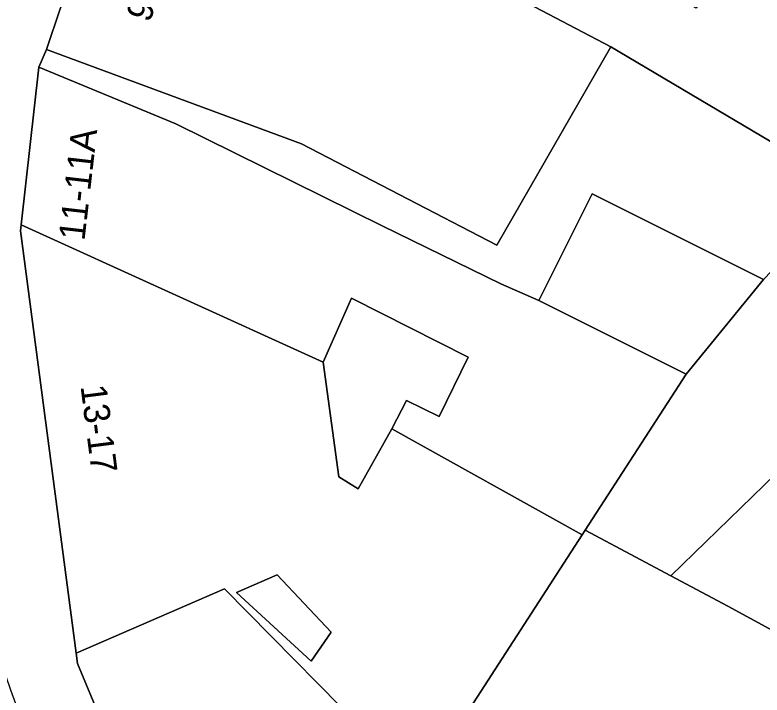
# Model space of a CAD drawing. Extents: x 160663 to 161506, y 382245 to 383291.
# Drawn here: x 161129.57 to 161158.3, y 383159.05 to 383185.21 of the extents above; entities that cross this region are included whole.
import ezdxf

# ---------------------------------------------------------------- set-up
doc = ezdxf.new("R2010")
doc.units = 0
for name, color, linetype in [('IMGEO_Erf', 7, 'Continuous'), ('IMGEO_Groenvoorziening', 7, 'Continuous'), ('IMGEO_Pand', 7, 'Continuous'), ('IMGEO_Pand_nummerreeks', 7, 'Continuous'), ('IMGEO_Parkeervlak_open', 7, 'Continuous'), ('IMGEO_Rijbaan_lokaal_open', 7, 'Continuous'), ('IMGEO_Woonerf_open', 7, 'Continuous')]:
    doc.layers.add(name, color=color, linetype=linetype)

msp = doc.modelspace()

# ---------------------------------------------------------------- linework, layer by layer
at = {"layer": 'IMGEO_Erf'}
for points in [[(161152.489, 383183.975), (161148.098, 383176.349), (161140.589, 383180.249), (161130.789, 383183.88), (161130.489, 383183.198), (161135.759, 383181.024), (161143.687, 383177.09), (161148.256, 383174.862), (161149.712, 383174.226), (161151.763, 383178.33), (161158.353, 383175.037), (161161.697, 383178.516)], [(161146.994, 383172.049), (161142.518, 383174.315), (161141.423, 383171.856), (161142.026, 383167.449), (161142.775, 383166.983), (161144.065, 383169.294), (161144.626, 383170.374), (161145.885, 383169.763)], [(161141.729, 383161.474), (161139.651, 383163.673), (161138.095, 383162.998), (161140.959, 383160.361)]]:
    msp.add_lwpolyline(points, close=True, dxfattribs=at)
at = {"layer": 'IMGEO_Groenvoorziening'}
msp.add_lwpolyline([(161159.601, 383161.046), (161156.987, 383162.473), (161154.786, 383163.643), (161151.498, 383165.39), (161151.378, 383165.212), (161146.783, 383158.104), (161149.389, 383151.959), (161150.771, 383148.7), (161150.848, 383148.779), (161151.214, 383148.74), (161151.442, 383143.355), (161142.883, 383135.27), (161146.227, 383132.301), (161147.528, 383133.493), (161149.889, 383137.24), (161153.216, 383142.573), (161155.564, 383146.324), (161155.876, 383146.12), (161165.215, 383155.885)], dxfattribs=at)
at = {"layer": 'IMGEO_Pand'}
for points in [[(161172.367, 383200.749), (161171.844, 383201.255), (161159.377, 383211.995), (161158.058, 383210.285), (161155.834, 383211.816), (161154.669, 383210.217), (161147.146, 383215.757), (161145.479, 383213.282), (161139.653, 383204.63), (161139.801, 383204.468), (161148.222, 383200.282), (161153.886, 383196.391), (161151.659, 383193.084), (161157.001, 383189.472), (161157.811, 383188.924), (161155.764, 383185.471), (161150.54, 383188.404), (161149.011, 383185.817), (161152.489, 383183.975), (161161.697, 383178.516), (161162.427, 383178.083), (161166.075, 383183.277), (161162.938, 383185.44), (161160.536, 383187.097)], [(161134.132, 383192.246), (161131.314, 383185.435), (161130.789, 383183.88), (161140.589, 383180.249), (161148.098, 383176.349), (161152.489, 383183.975), (161149.011, 383185.817), (161143.541, 383188.713)], [(161143.687, 383177.09), (161135.759, 383181.024), (161130.489, 383183.198), (161129.809, 383177.129), (161141.423, 383171.856), (161142.518, 383174.315), (161146.994, 383172.049), (161145.885, 383169.763), (161144.626, 383170.374), (161144.065, 383169.294), (161151.378, 383165.212), (161151.498, 383165.39), (161155.385, 383171.391), (161149.712, 383174.226), (161148.256, 383174.862)], [(161155.385, 383171.391), (161158.353, 383175.037), (161151.763, 383178.33), (161149.712, 383174.226)], [(161141.423, 383171.856), (161129.809, 383177.129), (161129.783, 383176.901), (161131.927, 383160.664), (161137.626, 383163.141), (161143.896, 383156.786), (161145.179, 383155.593), (161145.348, 383155.898), (161146.783, 383158.104), (161151.378, 383165.212), (161144.065, 383169.294), (161142.775, 383166.983), (161142.026, 383167.449)], [(161139.651, 383163.673), (161141.729, 383161.474), (161140.959, 383160.361), (161138.095, 383162.998)], [(161131.927, 383160.664), (161131.982, 383160.267), (161134.843, 383153.401), (161143.896, 383156.786), (161137.626, 383163.141)]]:
    msp.add_lwpolyline(points, close=True, dxfattribs=at)
at = {"layer": 'IMGEO_Parkeervlak_open'}
msp.add_lwpolyline([(161179.091, 383187.153), (161175.47, 383190.87), (161165.765, 383181.237), (161162.427, 383178.083), (161161.697, 383178.516), (161158.353, 383175.037), (161155.385, 383171.391), (161151.498, 383165.39), (161154.786, 383163.643), (161163.312, 383171.916), (161171.06, 383179.398)], close=True, dxfattribs=at)
at = {"layer": 'IMGEO_Rijbaan_lokaal_open'}
msp.add_lwpolyline([(161206.066, 383159.432), (161201.563, 383163.94), (161200.163, 383165.469), (161189.424, 383176.545), (161179.091, 383187.153), (161171.06, 383179.398), (161163.312, 383171.916), (161154.786, 383163.643), (161156.987, 383162.473), (161159.601, 383161.046)], dxfattribs=at)
at = {"layer": 'IMGEO_Woonerf_open'}
msp.add_lwpolyline([(161137.518, 383146.979), (161134.843, 383153.401), (161131.982, 383160.267), (161131.927, 383160.664), (161129.783, 383176.901), (161129.809, 383177.129), (161130.489, 383183.198), (161130.789, 383183.88), (161131.314, 383185.435), (161134.132, 383192.246), (161135.412, 383195.339), (161136.378, 383197.673), (161136.869, 383198.648), (161139.406, 383203.684), (161139.801, 383204.468), (161139.653, 383204.63), (161138.74, 383205.154), (161143.158, 383214.429), (161142.031, 383214.987), (161141.728, 383215.125), (161141.644, 383214.953), (161140.933, 383213.502), (161130.888, 383192.701)], dxfattribs=at)
for centre, radius, start, end in [((161170.895, 383174.782), 43.837, 155.8726, 168.4568), ((161170.895, 383174.782), 43.837, 155.8726, 168.4568), ((161171.449, 383174.177), 44.609, 179.4958, 202.4128), ((161171.449, 383174.177), 44.609, 179.4958, 202.4128)]:
    msp.add_arc(centre, radius, start, end, dxfattribs=at)

# ---------------------------------------------------------------- texts
at = {"layer": 'IMGEO_Pand_nummerreeks'}
for s, rotation, p in [('9-9A', 67.9412, (161134.731, 383184.874)), ('11-11A', 83.4112, (161132.245, 383176.5)), ('13-17', 277.3222, (161132.093, 383170.928))]:
    msp.add_text(s, height=1, rotation=rotation, dxfattribs=at).set_placement(p)

doc.saveas('drawing.dxf')
